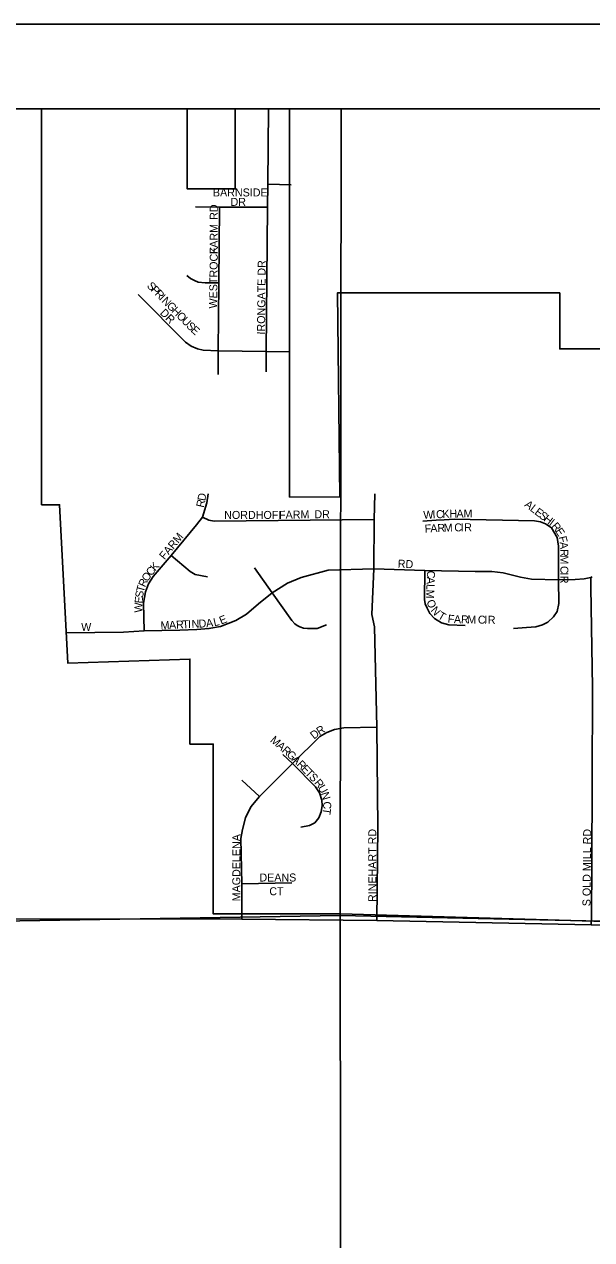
# Model space of a CAD drawing. Extents: x -209 to 4852, y 0 to 905.
# Drawn here: x 318.72 to 332.14, y 311.79 to 340.56 of the extents above; entities that cross this region are included whole.
import ezdxf

# ---------------------------------------------------------------- set-up
doc = ezdxf.new("R2010")
doc.units = 0
for name, color, linetype in [('Default', 7, 'Continuous'), ('GM_X_Airport_Location_Class_2', 7, 'Continuous'), ('GM_X_Airport_Location_Class_3', 7, 'Continuous'), ('GM_X_Minor_River', 7, 'Continuous'), ('GM_X_US_Location', 7, 'Continuous'), ('SH_Data', 7, 'Continuous')]:
    doc.layers.add(name, color=color, linetype=linetype)

msp = doc.modelspace()

# ---------------------------------------------------------------- linework, layer by layer
at = {"layer": 'Default'}
msp.add_lwpolyline([(390.832, 338.559), (254.832, 338.559), (254.832, 202.559), (390.832, 202.559)], close=True, dxfattribs=at)
at = {"layer": 'GM_X_Airport_Location_Class_2'}
for points in [[(324.437, 332.334), (324.435, 332.813), (324.466, 336.234), (324.477, 336.774), (324.49, 338.559)], [(324.477, 336.774), (325.028, 336.761)], [(322.767, 336.239), (323.33, 336.234), (324.466, 336.234)], [(323.301, 332.27), (323.298, 332.829), (323.316, 334.442), (323.33, 336.234)], [(322.559, 334.614), (322.649, 334.538), (322.739, 334.493), (322.826, 334.456), (322.995, 334.44), (323.316, 334.442)], [(321.411, 334.166), (322.525, 333.037), (322.666, 332.938), (322.816, 332.875), (322.947, 332.844), (323.298, 332.829), (324.435, 332.813), (324.988, 332.803)], [(321.548, 326.204), (321.536, 326.856), (321.58, 327.127), (321.65, 327.31), (321.763, 327.485), (322.188, 327.983), (322.785, 328.708), (322.934, 328.892), (323.03, 329.232), (323.065, 329.442)], [(327.054, 319.345), (327.08, 321.558), (327.058, 323.918), (326.999, 326.297), (326.94, 326.59), (326.985, 327.665), (326.991, 328.837), (327.01, 329.446)], [(322.934, 328.892), (323.084, 328.819), (323.208, 328.8), (326.991, 328.837)], [(328.139, 328.801), (328.456, 328.818), (328.65, 328.83), (328.885, 328.842), (330.783, 328.806), (330.924, 328.783), (331.048, 328.736)], [(330.29, 326.256), (330.595, 326.28), (330.819, 326.297), (330.977, 326.344), (331.101, 326.403), (331.236, 326.532), (331.318, 326.662), (331.359, 326.85), (331.356, 327.407), (331.353, 328.207), (331.324, 328.413), (331.183, 328.636), (331.048, 328.736)], [(322.188, 327.983), (322.641, 327.604), (322.759, 327.535), (323.047, 327.479)], [(319.707, 326.156), (321.063, 326.168), (321.548, 326.204), (322.397, 326.218), (322.796, 326.231), (323.083, 326.256), (323.357, 326.306), (323.719, 326.443), (323.968, 326.592), (324.255, 326.842), (324.579, 327.103), (324.94, 327.328), (325.265, 327.465), (325.901, 327.64), (326.985, 327.665), (328.191, 327.629), (329.381, 327.604), (329.776, 327.604), (330.047, 327.571), (330.45, 327.472), (330.714, 327.423), (331.356, 327.407), (331.75, 327.415), (331.956, 327.431), (332.115, 327.467)], [(324.579, 327.103), (324.158, 327.689)], [(328.191, 327.629), (328.184, 326.946), (328.199, 326.84), (328.243, 326.734), (328.305, 326.612), (328.415, 326.495), (328.588, 326.392), (328.757, 326.341), (329.142, 326.326)], [(332.13, 319.443), (332.141, 320.686), (332.149, 322.615), (332.16, 324.863), (332.119, 327.233), (332.115, 327.467), (332.145, 327.482)], [(324.579, 327.103), (325.045, 326.446), (325.114, 326.367), (325.169, 326.328), (325.232, 326.292), (325.317, 326.263), (325.411, 326.253), (325.64, 326.256), (325.862, 326.345)], [(323.862, 319.374), (323.86, 320.214), (323.84, 321.285), (323.879, 321.499), (323.947, 321.772), (324.074, 322.035), (324.278, 322.278), (325.057, 323.057), (325.71, 323.7), (325.875, 323.797), (326.051, 323.865), (326.275, 323.904), (327.058, 323.918)], [(325.254, 321.553), (325.464, 321.593), (325.588, 321.658), (325.686, 321.776), (325.738, 321.913), (325.758, 322.07), (325.751, 322.194), (325.699, 322.364), (325.601, 322.508), (325.057, 323.057), (324.83, 323.272)], [(324.278, 322.278), (323.86, 322.668)], [(323.86, 320.214), (325.04, 320.236)], [(316.179, 319.381), (316.179, 319.381), (323.862, 319.374), (327.054, 319.345), (332.128, 319.242), (336.751, 319.12), (345.265, 318.953), (348.297, 318.913), (351.368, 318.883), (353.631, 318.876)], [(332.128, 319.242), (332.13, 319.443)]]:
    msp.add_lwpolyline(points, dxfattribs=at)
at = {"layer": 'GM_X_Minor_River'}
for points in [[(326.211, 338.559), (306.379, 338.559), (306.294, 319.133), (326.186, 319.462)], [(347.007, 338.559), (326.211, 338.559), (326.186, 319.462), (346.887, 319.016)], [(306.294, 319.133), (326.186, 319.462), (326.211, 298.849), (306.169, 298.948)], [(326.186, 319.462), (346.887, 319.016), (346.745, 298.733), (326.211, 298.849)]]:
    msp.add_lwpolyline(points, close=True, dxfattribs=at)
at = {"layer": 'GM_X_US_Location'}
for points in [[(352.833, 310.021), (351.247, 318.735), (353.713, 318.705), (353.701, 318.797), (356.964, 318.729), (356.95, 322.046), (354.466, 322.071), (354.466, 322.706), (350.479, 322.708), (351.204, 318.981), (346.879, 319.001), (332.187, 319.329), (326.197, 319.5), (323.186, 319.5), (323.185, 323.521), (322.632, 323.521), (322.632, 325.533), (319.745, 325.432), (319.548, 329.185), (319.124, 329.185), (319.123, 338.559), (286.601, 338.559)], [(352.833, 310.021), (351.247, 318.735), (353.713, 318.705), (353.701, 318.797), (356.964, 318.729), (356.95, 322.046), (354.466, 322.071), (354.466, 322.706), (350.479, 322.708), (351.204, 318.981), (346.879, 319.001), (332.187, 319.329), (326.197, 319.5), (323.186, 319.5), (323.185, 323.521), (322.632, 323.521), (322.632, 325.533), (319.745, 325.432), (319.548, 329.185), (319.124, 329.185), (319.123, 338.559), (286.601, 338.559)], [(334.22, 332.874), (331.381, 332.874), (331.381, 334.199), (326.124, 334.2), (326.182, 329.373), (324.989, 329.366), (324.988, 338.559), (323.707, 338.559), (323.707, 336.661), (322.571, 336.661), (322.57, 338.559), (319.123, 338.559), (319.124, 329.185), (319.548, 329.185), (319.745, 325.432), (322.632, 325.533), (322.632, 323.521), (323.185, 323.521), (323.186, 319.5), (326.197, 319.5), (332.187, 319.329)], [(334.22, 332.874), (331.381, 332.874), (331.381, 334.199), (326.124, 334.2), (326.182, 329.373), (324.989, 329.366), (324.988, 338.559), (323.707, 338.559), (323.707, 336.661), (322.571, 336.661), (322.57, 338.559), (319.123, 338.559), (319.124, 329.185), (319.548, 329.185), (319.745, 325.432), (322.632, 325.533), (322.632, 323.521), (323.185, 323.521), (323.186, 319.5), (326.197, 319.5), (332.187, 319.329)]]:
    msp.add_lwpolyline(points, dxfattribs=at)
for points in [[(322.57, 338.559), (322.571, 336.661), (323.707, 336.661), (323.707, 338.559)], [(322.57, 338.559), (322.571, 336.661), (323.707, 336.661), (323.707, 338.559)], [(324.988, 338.559), (324.989, 329.366), (326.182, 329.373), (326.124, 334.2), (331.381, 334.199), (331.381, 332.874), (334.22, 332.874), (334.22, 333.377), (335.356, 333.377), (335.356, 333.971), (335.795, 333.971), (335.795, 335.546), (335.996, 335.546), (335.946, 338.559)], [(324.988, 338.559), (324.989, 329.366), (326.182, 329.373), (326.124, 334.2), (331.381, 334.199), (331.381, 332.874), (334.22, 332.874), (334.22, 333.377), (335.356, 333.377), (335.356, 333.971), (335.795, 333.971), (335.795, 335.546), (335.996, 335.546), (335.946, 338.559)]]:
    msp.add_lwpolyline(points, close=True, dxfattribs=at)
at = {"layer": 'SH_Data'}
for p, q in [((252.832, 340.559), (392.832, 340.559)), ((254.832, 338.559), (390.832, 338.559))]:
    msp.add_line(p, q, dxfattribs=at)

# ---------------------------------------------------------------- texts
at = {"layer": 'GM_X_Airport_Location_Class_3'}
for s, height, rotation, p in [('BARNSIDE', 0.1894, 0, (323.177, 336.484)), ('DR', 0.1894, 0, (323.594, 336.261)), ('RD', 0.1894, 90, (323.292, 335.931)), ('FARM', 0.1894, 90, (323.292, 335.115)), ('WESTROCK', 0.1894, 89.2479, (323.275, 333.831)), ('IRONGATE DR', 0.18939, 89.3908, (324.408, 333.215)), ('S', 0.189, 314.4978, (321.601, 334.354)), ('P', 0.189, 314.5143, (321.694, 334.259)), ('R', 0.189, 314.5021, (321.788, 334.164)), ('I', 0.189, 314.5056, (321.893, 334.057)), ('N', 0.189, 314.5056, (321.951, 333.998)), ('DR', 0.1894, 315, (321.91, 333.714)), ('G', 0.189, 314.5056, (322.068, 333.879)), ('H', 0.189, 314.5056, (322.185, 333.76)), ('O', 0.189, 314.5056, (322.302, 333.641)), ('U', 0.189, 314.5056, (322.419, 333.522)), ('S', 0.189, 314.4978, (322.535, 333.403)), ('E', 0.189, 318.0966, (322.638, 333.299)), ('D', 0.189, 80.7138, (322.995, 329.266)), ('R', 0.189, 77.2894, (322.96, 329.108)), ('A', 0.189, 322.5967, (330.532, 329.16)), ('L', 0.189, 322.5946, (330.664, 329.059)), ('NORDHOFF', 0.1894, 0, (323.444, 328.85)), ('FARM', 0.1894, 1.1685, (324.743, 328.85)), ('DR', 0.1894, 0, (325.577, 328.867)), ('W', 0.189, 2.6407, (328.159, 328.85)), ('I', 0.189, 2.6678, (328.375, 328.86)), ('C', 0.189, 2.6235, (328.459, 328.864)), ('K', 0.189, 2.6532, (328.609, 328.871)), ('H', 0.189, 1.6397, (328.774, 328.879)), ('A', 0.189, 0.0874, (328.939, 328.883)), ('M', 0.189, 0, (329.106, 328.884)), ('E', 0.189, 322.5936, (330.77, 328.978)), ('S', 0.189, 322.5936, (330.876, 328.897)), ('H', 0.189, 322.6026, (330.982, 328.816)), ('F', 0.189, 2.7328, (328.191, 328.525)), ('A', 0.189, 2.7326, (328.324, 328.531)), ('R', 0.189, 2.5993, (328.491, 328.539)), ('M', 0.189, 2.0584, (328.64, 328.546)), ('C', 0.189, 1.0443, (328.889, 328.554)), ('I', 0.189, 0.3496, (329.038, 328.557)), ('R', 0.189, 0.0972, (329.122, 328.558)), ('I', 0.189, 322.5967, (331.114, 328.715)), ('R', 0.189, 310.5644, (331.173, 328.671)), ('E', 0.189, 302.6745, (331.266, 328.563)), ('FARM', 0.1894, 50.1916, (322.033, 327.871)), ('F', 0.189, 282.8103, (331.353, 328.422)), ('A', 0.189, 274.4859, (331.382, 328.299)), ('R', 0.189, 270.6558, (331.395, 328.136)), ('C', 0.189, 51.1429, (321.721, 327.484)), ('K', 0.189, 50.0293, (321.815, 327.6)), ('RD', 0.1894, 356.989, (327.546, 327.7)), ('C', 0.189, 269.994, (331.396, 327.737)), ('M', 0.189, 270, (331.396, 327.987)), ('R', 0.189, 65.8797, (321.573, 327.221)), ('O', 0.189, 55.5219, (321.629, 327.35)), ('A', 0.189, 267.3582, (328.239, 327.479)), ('C', 0.189, 267.328, (328.246, 327.629)), ('I', 0.189, 270, (331.396, 327.587)), ('R', 0.189, 269.994, (331.396, 327.503)), ('S', 0.189, 82.1327, (321.523, 326.974)), ('T', 0.189, 74.9102, (321.54, 327.1)), ('M', 0.189, 267.3423, (328.225, 327.18)), ('L', 0.189, 267.3218, (328.232, 327.313)), ('W', 0.189, 89.2435, (321.508, 326.631)), ('E', 0.189, 84.5558, (321.511, 326.843)), ('O', 0.189, 288.9117, (328.227, 326.903)), ('E', 0.189, 21.8901, (323.372, 326.347)), ('N', 0.189, 309.9662, (328.318, 326.68)), ('T', 0.189, 330.4637, (328.482, 326.505)), ('F', 0.189, 353.2403, (328.723, 326.4)), ('A', 0.189, 358.7317, (328.876, 326.383)), ('R', 0.189, 359.1152, (329.044, 326.379)), ('M', 0.189, 359.1074, (329.194, 326.377)), ('C', 0.189, 359.1267, (329.444, 326.373)), ('I', 0.189, 359.0823, (329.594, 326.371)), ('R', 0.189, 359.1152, (329.677, 326.369)), ('W', 0.189, 0, (320.061, 326.2)), ('M', 0.189, 2.6787, (321.943, 326.234)), ('A', 0.189, 2.6671, (322.143, 326.243)), ('R', 0.189, 2.6773, (322.309, 326.251)), ('T', 0.189, 2.6782, (322.459, 326.258)), ('I', 0.189, 2.6681, (322.592, 326.264)), ('N', 0.189, 2.6757, (322.676, 326.268)), ('D', 0.189, 2.6671, (322.842, 326.276)), ('A', 0.189, 6.8585, (323.024, 326.285)), ('L', 0.189, 12.5048, (323.209, 326.308)), ('M', 0.189, 318.5434, (324.518, 323.591)), ('D', 0.189, 38.4482, (325.569, 323.624)), ('R', 0.189, 31.0221, (325.695, 323.724)), ('A', 0.189, 318.5574, (324.668, 323.459)), ('R', 0.189, 318.5399, (324.792, 323.349)), ('G', 0.189, 318.5407, (324.905, 323.249)), ('A', 0.189, 316.1591, (325.028, 323.14)), ('R', 0.189, 314.107, (325.147, 323.026)), ('E', 0.189, 313.8214, (325.251, 322.919)), ('T', 0.189, 313.8214, (325.344, 322.823)), ('S', 0.189, 313.8214, (325.436, 322.726)), ('R', 0.189, 310.0139, (325.561, 322.596)), ('U', 0.189, 299.9103, (325.652, 322.489)), ('N', 0.189, 286.672, (325.731, 322.355)), ('T', 0.189, 261.9974, (325.788, 322.017)), ('C', 0.189, 271.19, (325.784, 322.159)), ('MAGDELENA', 0.1894, 90, (323.825, 319.798)), ('RINEHART RD', 0.18939, 90, (327.042, 319.781)), ('S OLD MILL RD', 0.18939, 89.4281, (332.108, 319.681)), ('DEANS', 0.1894, 0, (324.277, 320.267)), ('CT', 0.1894, 0, (324.511, 319.941))]:
    msp.add_text(s, height=height, rotation=rotation, dxfattribs=at).set_placement(p)

doc.saveas('drawing.dxf')
